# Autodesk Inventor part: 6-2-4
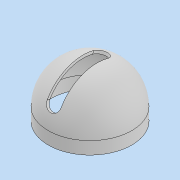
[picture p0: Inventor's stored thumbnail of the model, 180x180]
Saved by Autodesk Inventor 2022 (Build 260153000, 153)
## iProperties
Created: 2021-07
Part Number: 6-2-4
Material: 一般
Document SubType Name: Modeling
Designer: DesignLab
Density: 1 g/cm^3
Appearance: 既定
Author: DesignLab
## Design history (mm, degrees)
sketch "スケッチ1"
  geometry: L1 (0, 0)-(30, 0); L2 (0, 0)-(30, 0); L3 (0, 0)-(0, 30); L4 (30, 0)-(30, -9); L5 (30, -9)-(0, -9); L6 (0, -9)-(0, 30); A1 r 30 centre (0, 0) between (30, 0) and (0, 30); 2 further points
  constraints: 12 end point, 2 point on circle, 2 vertical, 1 centre point, 1 coincident, 1 collinear, 1 horizontal, 1 perpendicular
  dimensions: "d0" = 30 radius of A1; "d1" = 0 distance between parallel lines of L1 L2; "d2" = 90 deg angle of L1 L3; "d3" = 9 distance of L2.end L4.end
revolve "回転1" sketch "スケッチ1" stored, may be unused: angle "d4" = 90 deg
feature "シェル1" dims "d5" = 2
sketch "スケッチ2"
  geometry: L1 (-39.913, 14.527)-(0, 0); L2 (0, 0)-(18.157, 38.938); L3 (-28, 0)-(28, 0) reference; A1 r 30 centre (0, 0) between (30, 0) and (-30, 0) reference; 2 further points
  constraints: 4 end point
  dimensions: "d6" = 95 deg angle of L2 L1; "d7" = 20 deg angle of L1 L3
extrude "押し出し1" cut sketch "スケッチ2" stored distance "d8" = 10; taper "d9" = 0 deg
feature "フルラウンド フィレット1"
feature "フルラウンド フィレット2"
node "ソリッド1"
